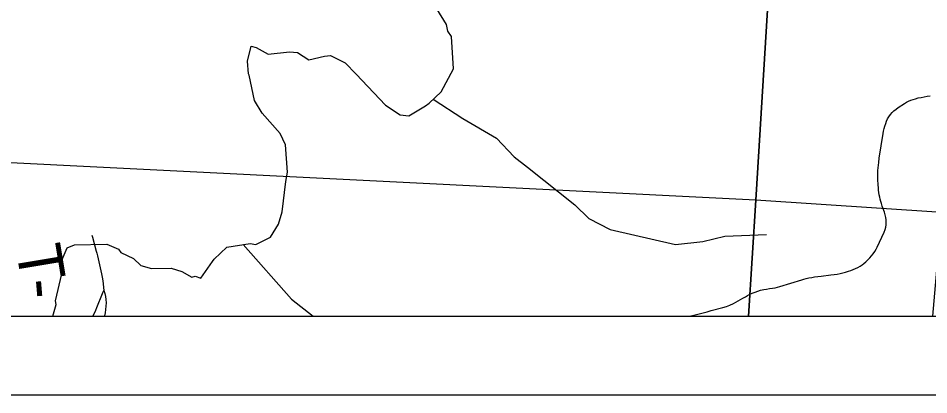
# Model space of a CAD drawing. Extents: x 0 to 34, y 0 to 22.
# Drawn here: x 2.913 to 4.072, y 14 to 14.479 of the extents above; entities that cross this region are included whole.
import ezdxf

# ---------------------------------------------------------------- set-up
doc = ezdxf.new("R2010")
doc.units = 0
for name, color, linetype in [('Default', 7, 'Continuous'), ('GM_X_Minor_River', 7, 'Continuous'), ('GM_X_Section', 7, 'Continuous'), ('GM_X_Township_Road', 7, 'Continuous'), ('GM_X_Township_Road_Text', 7, 'Continuous'), ('SH_Cut_Line', 7, 'Continuous'), ('SH_Data', 7, 'Continuous')]:
    doc.layers.add(name, color=color, linetype=linetype)

msp = doc.modelspace()

# ---------------------------------------------------------------- linework, layer by layer
at = {"layer": 'Default'}
for points in [[(2.1, 19.5179), (2.1, 14.1), (5.687, 14.1), (5.785, 14.1504), (5.9145, 14.1963), (5.9273, 14.1959), (5.9341, 14.3014), (6.0001, 15.328), (6.0418, 15.9539), (6.0633, 16.2368), (6.0901, 16.6706), (6.1151, 17.0743), (6.1723, 18.0255), (6.1917, 18.3385), (6.2282, 18.9116), (6.2536, 19.3066), (5.4875, 19.3459), (4.7013, 19.3856), (4.4284, 19.3984), (3.7007, 19.4348)], [(2.815, 14.1), (3.8426, 14.1), (3.8519, 14.2476), (2.8265, 14.2988)], [(3.8426, 14.1), (4.0772, 14.1), (4.0883, 14.232), (3.8519, 14.2476)]]:
    msp.add_lwpolyline(points, close=True, dxfattribs=at)
at = {"layer": 'GM_X_Minor_River'}
for points in [[(3.4671, 14.4145), (3.4643, 14.4559), (3.4598, 14.4624), (3.4579, 14.4711), (3.4458, 14.4912)], [(3.2558, 14.2832), (3.2531, 14.3178), (3.2463, 14.3322), (3.2236, 14.3584), (3.2138, 14.3743), (3.2069, 14.4066), (3.2062, 14.4085), (3.2046, 14.4245), (3.2095, 14.4435), (3.216, 14.442), (3.2311, 14.4333), (3.2583, 14.4364), (3.2685, 14.4353), (3.2829, 14.4262), (3.3029, 14.4308), (3.3105, 14.4316), (3.329, 14.4225), (3.343, 14.4077), (3.3805, 14.3683), (3.399, 14.3562), (3.4103, 14.3547), (3.4315, 14.3677), (3.436, 14.3711), (3.4511, 14.3856), (3.4671, 14.4145)], [(3.441, 14.3759), (3.4789, 14.3514), (3.5216, 14.3266), (3.5443, 14.3027), (3.5613, 14.2896), (3.6215, 14.2418), (3.6394, 14.2241), (3.6662, 14.2103), (3.7496, 14.191), (3.7845, 14.1948), (3.8123, 14.2019), (3.8652, 14.204)], [(2.9571, 14.1), (2.9611, 14.1149), (2.9604, 14.1194), (2.9683, 14.1537), (2.969, 14.1723), (2.9754, 14.1871), (2.9845, 14.1906), (3.0257, 14.1918), (3.0404, 14.1854), (3.0435, 14.1808), (3.0597, 14.1733), (3.0692, 14.1646), (3.0828, 14.1608), (3.1077, 14.1612), (3.1214, 14.1567), (3.1338, 14.1495), (3.138, 14.1511), (3.1452, 14.1484), (3.1603, 14.1694), (3.1625, 14.1724), (3.1784, 14.188), (3.2083, 14.1923), (3.2154, 14.1912), (3.234, 14.2007), (3.2441, 14.2171), (3.249, 14.2327), (3.2536, 14.2714), (3.2558, 14.2832)], [(3.1994, 14.191), (3.2606, 14.1218), (3.2882, 14.1)]]:
    msp.add_lwpolyline(points, dxfattribs=at)
at = {"layer": 'GM_X_Section'}
for points in [[(3.8776, 14.6701), (3.8519, 14.2476), (2.8265, 14.2988), (2.8494, 14.7254)], [(4.92, 14.6193), (4.8918, 14.1721), (4.0883, 14.232), (3.8519, 14.2476), (3.8776, 14.6701)]]:
    msp.add_lwpolyline(points, close=True, dxfattribs=at)
at = {"layer": 'GM_X_Township_Road'}
for points in [[(3.7658, 14.1), (3.7689, 14.1005), (3.7728, 14.1013), (3.7764, 14.1021), (3.79, 14.1057), (3.7948, 14.1071), (3.8096, 14.1109), (3.8145, 14.1124), (3.8185, 14.114), (3.8232, 14.1161), (3.8353, 14.1228), (3.8384, 14.1246), (3.8411, 14.1262), (3.8442, 14.1279), (3.8473, 14.1293), (3.8508, 14.1307), (3.8543, 14.1318), (3.8579, 14.1329), (3.8618, 14.1338), (3.8655, 14.1345), (3.8692, 14.135), (3.8731, 14.1355), (3.8764, 14.1362), (3.8795, 14.137), (3.8825, 14.1379), (3.9101, 14.1462), (3.913, 14.147), (3.9159, 14.1478), (3.9192, 14.1486), (3.9229, 14.1493), (3.9266, 14.1499), (3.9306, 14.1505), (3.9349, 14.151), (3.9473, 14.1524), (3.9513, 14.1529), (3.9553, 14.1535), (3.959, 14.1543), (3.9625, 14.1551), (3.9658, 14.156), (3.9697, 14.1572), (3.9726, 14.1582), (3.9755, 14.1593), (3.9785, 14.1605), (3.9816, 14.162), (3.9844, 14.1636), (3.9871, 14.1653), (3.9894, 14.1671), (3.9919, 14.1692), (3.9943, 14.1715), (3.9968, 14.1742), (3.9991, 14.1768), (4.0011, 14.1793), (4.0032, 14.1824), (4.005, 14.1854), (4.0063, 14.1879), (4.0152, 14.207), (4.0164, 14.2101), (4.0172, 14.2133), (4.0176, 14.2164), (4.0178, 14.2194), (4.0177, 14.2227), (4.0173, 14.2256), (4.0165, 14.229), (4.0155, 14.2323), (4.0127, 14.24), (4.0116, 14.2432), (4.0108, 14.2458), (4.01, 14.2487), (4.0094, 14.2515), (4.0088, 14.2544), (4.0084, 14.2575), (4.008, 14.2603), (4.0078, 14.263), (4.0073, 14.2677), (4.007, 14.2733), (4.0069, 14.2781), (4.007, 14.2817), (4.0072, 14.2855), (4.0075, 14.2887), (4.0082, 14.2954), (4.0089, 14.3011), (4.0137, 14.3322), (4.0143, 14.3354), (4.015, 14.3387), (4.0159, 14.3419), (4.017, 14.3451), (4.0181, 14.3481), (4.0194, 14.3509), (4.021, 14.3538), (4.023, 14.3566), (4.0252, 14.3592), (4.0275, 14.3613), (4.0302, 14.3635), (4.0331, 14.3655), (4.041, 14.3705), (4.0435, 14.3721), (4.0461, 14.3734), (4.0489, 14.3746), (4.0518, 14.3758), (4.055, 14.3767), (4.0584, 14.3776), (4.062, 14.3784), (4.066, 14.3792), (4.0698, 14.3799), (4.0737, 14.3805)], [(3.0067, 14.2031), (3.0074, 14.2007), (3.0123, 14.1828), (3.013, 14.18), (3.0138, 14.1768), (3.0189, 14.1538), (3.0198, 14.1496), (3.0205, 14.1448), (3.022, 14.1325), (3.0231, 14.129), (3.0241, 14.1252), (3.0246, 14.1211), (3.0248, 14.1169), (3.0247, 14.1128), (3.0242, 14.1084), (3.0236, 14.1042), (3.0228, 14.1006), (3.0227, 14.1)], [(3.0078, 14.1), (3.0099, 14.104), (3.0117, 14.1077), (3.0132, 14.1111), (3.0201, 14.1288), (3.0208, 14.1303), (3.022, 14.1325)]]:
    msp.add_lwpolyline(points, dxfattribs=at)
at = {"layer": 'SH_Cut_Line'}
msp.add_lwpolyline([(2.1, 20.9), (2.1, 14.1), (5.687, 14.1)], dxfattribs=at)
at = {"layer": 'SH_Data'}
for p, q in [((2.1, 14.1), (8.9, 14.1)), ((2, 14), (9, 14))]:
    msp.add_line(p, q, dxfattribs=at)

# ---------------------------------------------------------------- texts
at = {"layer": 'GM_X_Township_Road_Text'}
for s, rotation, p in [('T', 279.4324, (2.9099, 14.1864)), ('-', 274.7672, (2.9167, 14.1457))]:
    msp.add_text(s, height=0.0568, rotation=rotation, dxfattribs=at).set_placement(p)

doc.saveas('drawing.dxf')
